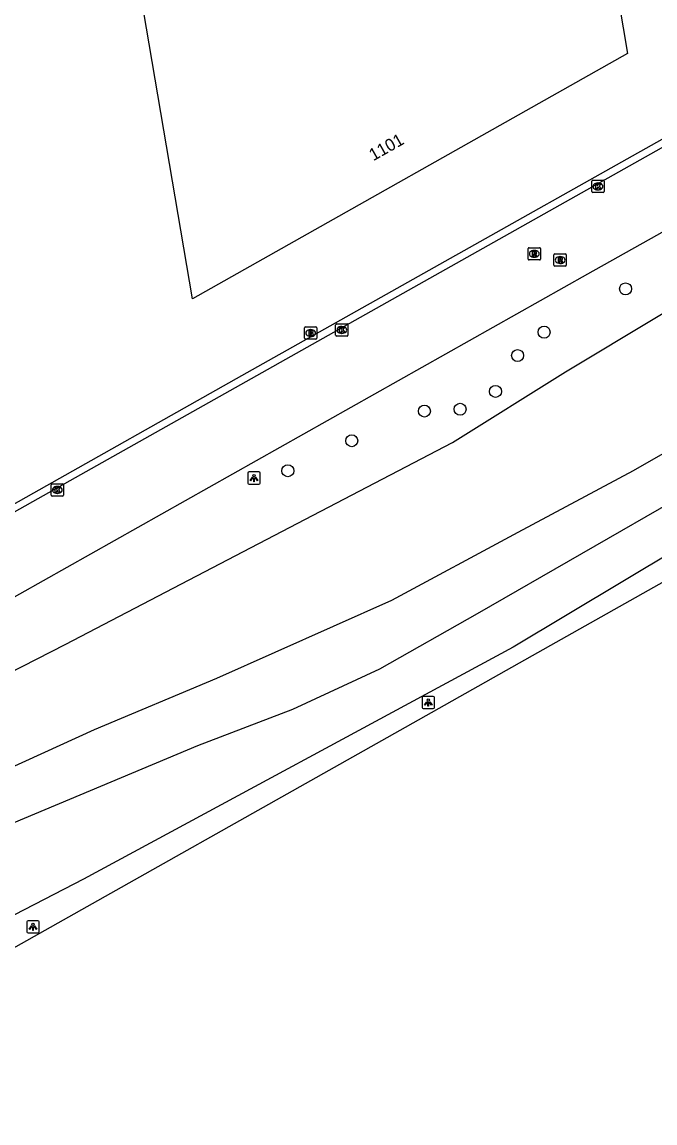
# Model space of a CAD drawing. Extents: x 154324 to 155743, y 382939 to 384183.
# Drawn here: x 154876.6 to 154928.1, y 383096.6 to 383186.4 of the extents above; entities that cross this region are included whole.
import ezdxf

# ---------------------------------------------------------------- set-up
doc = ezdxf.new("R2010")
doc.units = 0
for name, color, linetype in [('IMGEO_Berm_groen', 7, 'Continuous'), ('IMGEO_Boom', 7, 'Continuous'), ('IMGEO_Brandkraan', 7, 'Continuous'), ('IMGEO_Fietspad_gesloten', 7, 'Continuous'), ('IMGEO_Greppel_droge_sloot', 7, 'Continuous'), ('IMGEO_Kolk', 7, 'Continuous'), ('IMGEO_Lichtpunt', 7, 'Continuous'), ('IMGEO_Pand', 7, 'Continuous'), ('IMGEO_Pand_nummerreeks', 7, 'Continuous'), ('IMGEO_Rijbaan_lokaal_gesloten', 7, 'Continuous'), ('IMGEO_Rijbaan_lokaal_open', 7, 'Continuous'), ('IMGEO_Rioolput', 7, 'Continuous')]:
    doc.layers.add(name, color=color, linetype=linetype)

msp = doc.modelspace()

# ---------------------------------------------------------------- linework, layer by layer
at = {"layer": 'IMGEO_Berm_groen'}
for points in [[(154814.014, 383102.45), (154825.93, 383109.313), (154838.85, 383113.673), (154847.481, 383118.927), (154880.084, 383135.612), (154911.651, 383152.085), (154920.843, 383157.863), (154951.174, 383176.097), (154968.508, 383188.95), (154984.993, 383198.511)], [(154997.792, 383187.521), (154995.02, 383185.463), (154993.143, 383185.64), (154991.722, 383185.985), (154990.932, 383185.043), (154990.625, 383183.53), (154987.222, 383179.751), (154971.409, 383172.227), (154963.03, 383164.911), (154934.465, 383146.125), (154916.586, 383135.416), (154881.582, 383116.493), (154841.437, 383095.734), (154819.252, 383088.815), (154813.096, 383089.869), (154809.33, 383090.404), (154807.247, 383092.596)]]:
    msp.add_lwpolyline(points, dxfattribs=at)
at = {"layer": 'IMGEO_Boom'}
for centre in [(154925.748, 383164.618), (154919.112, 383161.086), (154916.951, 383159.18), (154915.15, 383156.262), (154909.355, 383154.657), (154912.268, 383154.801), (154903.44, 383152.237), (154898.233, 383149.792)]:
    msp.add_circle(centre, 0.489, dxfattribs=at)
at = {"layer": 'IMGEO_Brandkraan'}
for p, q in [((154899.594, 383160.592), (154899.594, 383161.444)), ((154899.669, 383161.518), (154900.521, 383161.518)), ((154900.082, 383161.298), (154900.107, 383161.298)), ((154900.595, 383161.444), (154900.595, 383160.592)), ((154900.521, 383160.518), (154899.669, 383160.518)), ((154900.105, 383160.738), (154900.08, 383160.738))]:
    msp.add_line(p, q, dxfattribs=at)
for points in [[(154899.594, 383160.592), (154899.594, 383161.444)], [(154899.669, 383161.518), (154900.521, 383161.518)], [(154899.942, 383161.218), (154899.942, 383160.818), (154900.155, 383160.818)], [(154900.173, 383161.218), (154899.942, 383161.218)], [(154900.121, 383161.137), (154900.067, 383161.137), (154900.067, 383161.061)], [(154900.595, 383161.444), (154900.595, 383160.592)], [(154900.521, 383160.518), (154899.669, 383160.518)], [(154900.067, 383161.061), (154900.12, 383161.061)], [(154900.129, 383160.985), (154900.067, 383160.985), (154900.067, 383160.904)], [(154900.067, 383160.904), (154900.129, 383160.904)]]:
    msp.add_lwpolyline(points, dxfattribs=at)
for centre, radius, start, end in [((154899.671, 383161.442), 0.0765, 91.55205, 178.44795), ((154899.671, 383161.442), 0.0765, 91.55205, 178.44795), ((154900.122, 383161.099), 0.0379, 267.82845, 90.93552), ((154900.177, 383161.073), 0.145, 59.4692, 91.53667), ((154900.202, 383161.12), 0.0922, 285.51372, 58.15012), ((154900.519, 383161.442), 0.0765, 1.55205, 88.44795), ((154900.519, 383161.442), 0.0765, 1.55205, 88.44795), ((154899.671, 383160.594), 0.0765, 181.55205, 268.44795), ((154899.671, 383160.594), 0.0765, 181.55205, 268.44795), ((154900.13, 383160.944), 0.0404, 269.87594, 90.50774), ((154900.161, 383161.069), 0.251, 268.66757, 293.53466), ((154900.207, 383160.928), 0.105, 301.31148, 78.98903), ((154900.519, 383160.594), 0.0765, 271.55205, 358.44795), ((154900.519, 383160.594), 0.0765, 271.55205, 358.44795)]:
    msp.add_arc(centre, radius, start, end, dxfattribs=at)
for centre, major_axis, ratio, start_param, end_param in [((154900.081, 383161.018), (-0.387, 0.002), 0.722429, 4.712389, 7.853982), ((154900.106, 383161.018), (-0.39, 0.002), 0.717154, 1.570796, 4.712389)]:
    msp.add_ellipse(centre, major_axis=major_axis, ratio=ratio, start_param=start_param, end_param=end_param, dxfattribs=at)
at = {"layer": 'IMGEO_Fietspad_gesloten'}
msp.add_lwpolyline([(155010.145, 383186.734), (155003.66, 383182.913), (154999.999, 383180.835), (154918.152, 383134.697), (154907.791, 383128.856), (154806.83, 383071.943)], dxfattribs=at)
at = {"layer": 'IMGEO_Greppel_droge_sloot'}
for points in [[(154872.512, 383124.159), (154882.484, 383128.684), (154892.456, 383132.874), (154906.701, 383139.242), (154917.009, 383144.773), (154926.394, 383149.801), (154931.841, 383152.944), (154934.229, 383155.332), (154938.922, 383157.343), (154942.484, 383160.15), (154947.134, 383163.837), (154951.199, 383167.944), (154955.85, 383172.762), (154959.935, 383177.099), (154962.951, 383179.529), (154967.665, 383182.147), (154967.917, 383182.734), (154970.472, 383185.122), (154973.196, 383186.798)], [(154930.668, 383147.895), (154913.657, 383138.132), (154905.696, 383133.607), (154898.615, 383130.339), (154890.863, 383127.364), (154875.905, 383121.079), (154866.143, 383116.805), (154859.942, 383114.752), (154854.83, 383112.699), (154843.852, 383108.3), (154835.975, 383104.78), (154831.911, 383102.978), (154824.704, 383100.045), (154819.593, 383098.034)]]:
    msp.add_lwpolyline(points, dxfattribs=at)
at = {"layer": 'IMGEO_Kolk'}
for p, q in [((154922.995, 383172.545), (154922.995, 383173.397)), ((154923.07, 383173.471), (154923.922, 383173.471)), ((154923.483, 383173.251), (154923.508, 383173.251)), ((154923.996, 383173.397), (154923.996, 383172.545)), ((154923.922, 383172.471), (154923.07, 383172.471)), ((154923.506, 383172.691), (154923.481, 383172.691)), ((154902.131, 383160.84), (154902.131, 383161.692)), ((154902.206, 383161.766), (154903.058, 383161.766)), ((154902.619, 383161.546), (154902.644, 383161.546)), ((154903.132, 383161.692), (154903.132, 383160.84)), ((154903.058, 383160.766), (154902.206, 383160.766)), ((154902.642, 383160.986), (154902.617, 383160.986)), ((154878.952, 383147.798), (154878.952, 383148.65)), ((154879.027, 383148.724), (154879.879, 383148.724)), ((154879.953, 383148.65), (154879.953, 383147.798)), ((154879.879, 383147.724), (154879.027, 383147.724)), ((154879.463, 383147.944), (154879.438, 383147.944)), ((154879.44, 383148.504), (154879.465, 383148.504))]:
    msp.add_line(p, q, dxfattribs=at)
for points in [[(154922.995, 383172.545), (154922.995, 383173.397)], [(154923.07, 383173.471), (154923.922, 383173.471)], [(154923.316, 383173.171), (154923.439, 383173.171), (154923.439, 383173.02), (154923.569, 383173.171), (154923.733, 383173.171), (154923.587, 383173.02), (154923.74, 383172.771), (154923.588, 383172.771), (154923.503, 383172.935), (154923.439, 383172.868), (154923.439, 383172.771), (154923.316, 383172.771), (154923.316, 383173.171)], [(154923.996, 383173.397), (154923.996, 383172.545)], [(154923.922, 383172.471), (154923.07, 383172.471)], [(154902.131, 383160.84), (154902.131, 383161.692)], [(154902.206, 383161.766), (154903.058, 383161.766)], [(154902.452, 383161.466), (154902.575, 383161.466), (154902.575, 383161.315), (154902.705, 383161.466), (154902.869, 383161.466), (154902.723, 383161.315), (154902.876, 383161.066), (154902.724, 383161.066), (154902.639, 383161.23), (154902.575, 383161.163), (154902.575, 383161.066), (154902.452, 383161.066), (154902.452, 383161.466)], [(154903.132, 383161.692), (154903.132, 383160.84)], [(154903.058, 383160.766), (154902.206, 383160.766)], [(154878.952, 383147.798), (154878.952, 383148.65)], [(154879.027, 383148.724), (154879.879, 383148.724)], [(154879.953, 383148.65), (154879.953, 383147.798)], [(154879.879, 383147.724), (154879.027, 383147.724)], [(154879.273, 383148.424), (154879.396, 383148.424), (154879.396, 383148.273), (154879.526, 383148.424), (154879.69, 383148.424), (154879.544, 383148.273), (154879.697, 383148.024), (154879.545, 383148.024), (154879.46, 383148.188), (154879.396, 383148.121), (154879.396, 383148.024), (154879.273, 383148.024), (154879.273, 383148.424)]]:
    msp.add_lwpolyline(points, dxfattribs=at)
for centre, start, end in [((154923.072, 383173.395), 91.55205, 178.44795), ((154923.072, 383173.395), 91.55205, 178.44795), ((154923.92, 383173.395), 1.55205, 88.44795), ((154923.92, 383173.395), 1.55205, 88.44795), ((154923.072, 383172.547), 181.55205, 268.44795), ((154923.072, 383172.547), 181.55205, 268.44795), ((154923.92, 383172.547), 271.55205, 358.44795), ((154923.92, 383172.547), 271.55205, 358.44795), ((154902.208, 383161.69), 91.55205, 178.44795), ((154902.208, 383161.69), 91.55205, 178.44795), ((154903.056, 383161.69), 1.55205, 88.44795), ((154903.056, 383161.69), 1.55205, 88.44795), ((154902.208, 383160.842), 181.55205, 268.44795), ((154902.208, 383160.842), 181.55205, 268.44795), ((154903.056, 383160.842), 271.55205, 358.44795), ((154903.056, 383160.842), 271.55205, 358.44795), ((154879.029, 383148.648), 91.55205, 178.44795), ((154879.029, 383148.648), 91.55205, 178.44795), ((154879.877, 383148.648), 1.55205, 88.44795), ((154879.877, 383148.648), 1.55205, 88.44795), ((154879.029, 383147.8), 181.55205, 268.44795), ((154879.029, 383147.8), 181.55205, 268.44795), ((154879.877, 383147.8), 271.55205, 358.44795), ((154879.877, 383147.8), 271.55205, 358.44795)]:
    msp.add_arc(centre, 0.0765, start, end, dxfattribs=at)
for centre, major_axis, ratio, start_param, end_param in [((154923.482, 383172.971), (-0.387, 0.002), 0.722429, 4.712389, 7.853982), ((154923.507, 383172.971), (-0.39, 0.002), 0.717154, 1.570796, 4.712389), ((154902.618, 383161.266), (-0.387, 0.002), 0.722429, 4.712389, 7.853982), ((154902.643, 383161.266), (-0.39, 0.002), 0.717154, 1.570796, 4.712389), ((154879.439, 383148.224), (-0.387, 0.002), 0.722429, 4.712389, 7.853982), ((154879.464, 383148.224), (-0.39, 0.002), 0.717154, 1.570796, 4.712389)]:
    msp.add_ellipse(centre, major_axis=major_axis, ratio=ratio, start_param=start_param, end_param=end_param, dxfattribs=at)
at = {"layer": 'IMGEO_Lichtpunt'}
for p, q in [((154894.98, 383149.594), (154894.98, 383148.787)), ((154894.98, 383149.594), (154894.98, 383148.787)), ((154895.882, 383149.689), (154895.074, 383149.689)), ((154895.882, 383149.689), (154895.074, 383149.689)), ((154895.976, 383148.787), (154895.976, 383149.594)), ((154895.976, 383148.787), (154895.976, 383149.594)), ((154895.074, 383148.693), (154895.882, 383148.693)), ((154895.074, 383148.693), (154895.882, 383148.693)), ((154909.175, 383131.297), (154909.175, 383130.49)), ((154909.175, 383131.297), (154909.175, 383130.49)), ((154910.077, 383131.392), (154909.269, 383131.392)), ((154910.077, 383131.392), (154909.269, 383131.392)), ((154910.171, 383130.49), (154910.171, 383131.297)), ((154910.171, 383130.49), (154910.171, 383131.297)), ((154909.269, 383130.396), (154910.077, 383130.396)), ((154909.269, 383130.396), (154910.077, 383130.396)), ((154876.975, 383113.014), (154876.975, 383112.207)), ((154876.975, 383113.014), (154876.975, 383112.207)), ((154877.877, 383113.109), (154877.069, 383113.109)), ((154877.877, 383113.109), (154877.069, 383113.109)), ((154877.971, 383112.207), (154877.971, 383113.014)), ((154877.971, 383112.207), (154877.971, 383113.014)), ((154877.069, 383112.113), (154877.877, 383112.113)), ((154877.069, 383112.113), (154877.877, 383112.113))]:
    msp.add_line(p, q, dxfattribs=at)
for points in [[(154895.354, 383149.258), (154895.393, 383149.23), (154895.205, 383148.968), (154895.167, 383148.995), (154895.354, 383149.258)], [(154895.456, 383149.21), (154895.503, 383149.21), (154895.503, 383148.888), (154895.456, 383148.888), (154895.456, 383149.21)], [(154895.566, 383149.23), (154895.604, 383149.257), (154895.791, 383148.995), (154895.752, 383148.967), (154895.566, 383149.23)], [(154909.549, 383130.961), (154909.588, 383130.933), (154909.4, 383130.671), (154909.362, 383130.698), (154909.549, 383130.961)], [(154909.651, 383130.913), (154909.698, 383130.913), (154909.698, 383130.591), (154909.651, 383130.591), (154909.651, 383130.913)], [(154909.761, 383130.933), (154909.799, 383130.96), (154909.986, 383130.698), (154909.947, 383130.67), (154909.761, 383130.933)], [(154877.349, 383112.678), (154877.388, 383112.65), (154877.2, 383112.388), (154877.162, 383112.415), (154877.349, 383112.678)], [(154877.451, 383112.63), (154877.498, 383112.63), (154877.498, 383112.308), (154877.451, 383112.308), (154877.451, 383112.63)], [(154877.561, 383112.65), (154877.599, 383112.677), (154877.786, 383112.415), (154877.747, 383112.387), (154877.561, 383112.65)]]:
    msp.add_lwpolyline(points, dxfattribs=at)
for centre in [(154895.479, 383149.392), (154909.674, 383131.095), (154877.474, 383112.812)]:
    msp.add_circle(centre, 0.0994, dxfattribs=at)
for centre, start, end in [((154895.074, 383149.594), 90, 180), ((154895.074, 383149.594), 90, 180), ((154895.882, 383149.594), 0, 90), ((154895.882, 383149.594), 0, 90), ((154895.074, 383148.787), 180, 270), ((154895.074, 383148.787), 180, 270), ((154895.882, 383148.787), 270, 0), ((154895.882, 383148.787), 270, 360), ((154909.269, 383131.297), 90, 180), ((154909.269, 383131.297), 90, 180), ((154910.077, 383131.297), 0, 90), ((154910.077, 383131.297), 0, 90), ((154909.269, 383130.49), 180, 270), ((154909.269, 383130.49), 180, 270), ((154910.077, 383130.49), 270, 0), ((154910.077, 383130.49), 270, 360), ((154877.069, 383113.014), 90, 180), ((154877.069, 383113.014), 90, 180), ((154877.877, 383113.014), 0, 90), ((154877.877, 383113.014), 0, 90), ((154877.069, 383112.207), 180, 270), ((154877.069, 383112.207), 180, 270), ((154877.877, 383112.207), 270, 0), ((154877.877, 383112.207), 270, 360)]:
    msp.add_arc(centre, 0.0946, start, end, dxfattribs=at)
at = {"layer": 'IMGEO_Pand'}
msp.add_lwpolyline([(154923.048, 383200.725), (154925.906, 383183.809), (154890.471, 383163.81), (154885.296, 383194.216)], dxfattribs=at)
at = {"layer": 'IMGEO_Rijbaan_lokaal_gesloten'}
for points in [[(154991.527, 383204.587), (154991.288, 383204.465), (154988.643, 383202.929), (154972.989, 383194.067), (154922.655, 383165.821), (154870.558, 383136.478), (154807.99, 383101.454), (154807.406, 383100.983), (154799.353, 383096.592), (154796.646, 383095.015), (154788.616, 383090.336), (154781.163, 383085.993), (154710.177, 383044.63)], [(154950.17, 383188.22), (154949.49, 383187.837), (154947.078, 383186.481), (154867.234, 383141.522), (154850.148, 383131.904), (154814.791, 383112.011)]]:
    msp.add_lwpolyline(points, dxfattribs=at)
at = {"layer": 'IMGEO_Rijbaan_lokaal_open'}
msp.add_lwpolyline([(154813.974, 383112.216), (154836.964, 383125.071), (154866.961, 383142.012), (154876.909, 383147.63), (154894.042, 383157.306), (154944.858, 383185.904), (154948.906, 383188.107)], dxfattribs=at)
at = {"layer": 'IMGEO_Rioolput'}
for p, q in [((154917.809, 383167.046), (154917.809, 383167.898)), ((154917.884, 383167.972), (154918.736, 383167.972)), ((154918.297, 383167.752), (154918.322, 383167.752)), ((154918.81, 383167.898), (154918.81, 383167.046)), ((154919.917, 383166.543), (154919.917, 383167.395)), ((154919.992, 383167.469), (154920.844, 383167.469)), ((154920.918, 383167.395), (154920.918, 383166.543)), ((154918.736, 383166.972), (154917.884, 383166.972)), ((154918.32, 383167.192), (154918.295, 383167.192)), ((154920.428, 383166.689), (154920.403, 383166.689)), ((154920.405, 383167.249), (154920.43, 383167.249)), ((154920.844, 383166.469), (154919.992, 383166.469))]:
    msp.add_line(p, q, dxfattribs=at)
for points in [[(154917.809, 383167.046), (154917.809, 383167.898)], [(154917.884, 383167.972), (154918.736, 383167.972)], [(154918.398, 383167.67), (154918.146, 383167.672), (154918.146, 383167.272)], [(154918.146, 383167.272), (154918.27, 383167.272), (154918.27, 383167.434), (154918.281, 383167.434)], [(154918.324, 383167.591), (154918.27, 383167.591), (154918.27, 383167.51)], [(154918.27, 383167.51), (154918.322, 383167.51)], [(154918.328, 383167.405), (154918.399, 383167.272), (154918.539, 383167.272), (154918.474, 383167.398)], [(154918.81, 383167.898), (154918.81, 383167.046)], [(154919.917, 383166.543), (154919.917, 383167.395)], [(154919.992, 383167.469), (154920.844, 383167.469)], [(154920.918, 383167.395), (154920.918, 383166.543)], [(154918.736, 383166.972), (154917.884, 383166.972)], [(154920.506, 383167.167), (154920.254, 383167.169), (154920.254, 383166.769)], [(154920.254, 383166.769), (154920.378, 383166.769), (154920.378, 383166.931), (154920.389, 383166.931)], [(154920.432, 383167.088), (154920.378, 383167.088), (154920.378, 383167.007)], [(154920.378, 383167.007), (154920.43, 383167.007)], [(154920.436, 383166.902), (154920.507, 383166.769), (154920.647, 383166.769), (154920.582, 383166.895)], [(154920.844, 383166.469), (154919.992, 383166.469)]]:
    msp.add_lwpolyline(points, dxfattribs=at)
for centre, radius, start, end in [((154917.886, 383167.896), 0.0765, 91.55205, 178.44795), ((154917.886, 383167.896), 0.0765, 91.55205, 178.44795), ((154918.28, 383167.381), 0.0533, 26.02933, 88.69889), ((154918.306, 383167.699), 0.19, 274.7715, 282.96867), ((154918.33, 383167.495), 0.0964, 77.00612, 93.18647), ((154918.344, 383167.552), 0.0378, 276.66336, 79.67722), ((154918.397, 383167.56), 0.109, 350.36119, 89.41601), ((154918.395, 383167.56), 0.112, 277.58423, 350.98172), ((154918.379, 383167.345), 0.108, 29.51342, 73.79051), ((154918.734, 383167.896), 0.0765, 1.55205, 88.44795), ((154918.734, 383167.896), 0.0765, 1.55205, 88.44795), ((154919.994, 383167.393), 0.0765, 91.55205, 178.44795), ((154919.994, 383167.393), 0.0765, 91.55205, 178.44795), ((154920.842, 383167.393), 0.0765, 1.55205, 88.44795), ((154920.842, 383167.393), 0.0765, 1.55205, 88.44795), ((154917.886, 383167.048), 0.0765, 181.55205, 268.44795), ((154917.886, 383167.048), 0.0765, 181.55205, 268.44795), ((154918.734, 383167.048), 0.0765, 271.55205, 358.44795), ((154918.734, 383167.048), 0.0765, 271.55205, 358.44795), ((154919.994, 383166.545), 0.0765, 181.55205, 268.44795), ((154919.994, 383166.545), 0.0765, 181.55205, 268.44795), ((154920.388, 383166.878), 0.0533, 26.02933, 88.69889), ((154920.414, 383167.196), 0.19, 274.7715, 282.96867), ((154920.438, 383166.992), 0.0964, 77.00612, 93.18647), ((154920.452, 383167.049), 0.0378, 276.66336, 79.67722), ((154920.505, 383167.057), 0.109, 350.36119, 89.41601), ((154920.503, 383167.057), 0.112, 277.58423, 350.98172), ((154920.487, 383166.842), 0.108, 29.51342, 73.79051), ((154920.842, 383166.545), 0.0765, 271.55205, 358.44795), ((154920.842, 383166.545), 0.0765, 271.55205, 358.44795)]:
    msp.add_arc(centre, radius, start, end, dxfattribs=at)
for centre, major_axis, ratio, start_param, end_param in [((154918.296, 383167.472), (-0.387, 0.002), 0.722429, 4.712389, 7.853982), ((154918.321, 383167.472), (-0.39, 0.002), 0.717154, 1.570796, 4.712389), ((154920.404, 383166.969), (-0.387, 0.002), 0.722429, 4.712389, 7.853982), ((154920.429, 383166.969), (-0.39, 0.002), 0.717154, 1.570796, 4.712389)]:
    msp.add_ellipse(centre, major_axis=major_axis, ratio=ratio, start_param=start_param, end_param=end_param, dxfattribs=at)

# ---------------------------------------------------------------- texts
at = {"layer": 'IMGEO_Pand_nummerreeks'}
msp.add_text('1101', height=1, rotation=29.43857, dxfattribs=at).set_placement((154905.2, 383175.017))

doc.saveas('drawing.dxf')
